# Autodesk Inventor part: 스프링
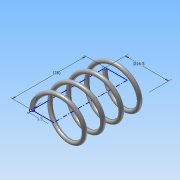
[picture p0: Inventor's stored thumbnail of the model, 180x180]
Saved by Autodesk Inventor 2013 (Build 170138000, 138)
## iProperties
Created: 2015-08
Part Number: 스프링
Material: 강철, 연강
Document SubType Name: Modeling
Designer: Administrator
Density: 7.86 g/cm^3
Mass: 2.84772 g
Surface Area: 9.78618 cm^2
Volume: 0.362305 cm^3
Author: Administrator
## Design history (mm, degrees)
sketch "스케치1"
  geometry: L1 (0, 0)-(-8.25, 0); L2 (-8.25, 0)-(-8.25, 28); L3 (-8.25, 28)-(0, 28); L4 (0, 28)-(0, 0); C1 r 0.75 at (-8.25, 0)
  constraints: 8 end point, 2 parallel, 1 centre point, 1 coincident, 1 horizontal, 1 perpendicular
  dimensions: "d5" = 16.5 diameter of L2 L4; "d7" = 28 distance of L1.end L2.end (derived); "d8" = 1.5 diameter of C1
feature "코일1" sketch "스케치1" pitch "d9" = 10; turns "d11" = 4; dims "d10" = 28 (= d7), "d12" = 0, angle "d13" = 90 deg, angle "d14" = 90 deg, "d15" = 0, "d16" = 0
sketch "스케치2"
  geometry: L1 (0, -12.5)-(28, -12.5); L2 (28, -12.5)-(28, 12.5); L3 (28, 12.5)-(0, 12.5); L4 (0, 12.5)-(0, -12.5); 4 further points
  constraints: 8 end point, 2 coincident, 2 midpoint, 2 parallel, 1 horizontal, 1 perpendicular
  dimensions: "d17" = 25 distance of L1.end L2.end
extrude "돌출1" sketch "스케치2" stored distance "d19" = 0; taper "d20" = 0 deg
node "솔리드1"
